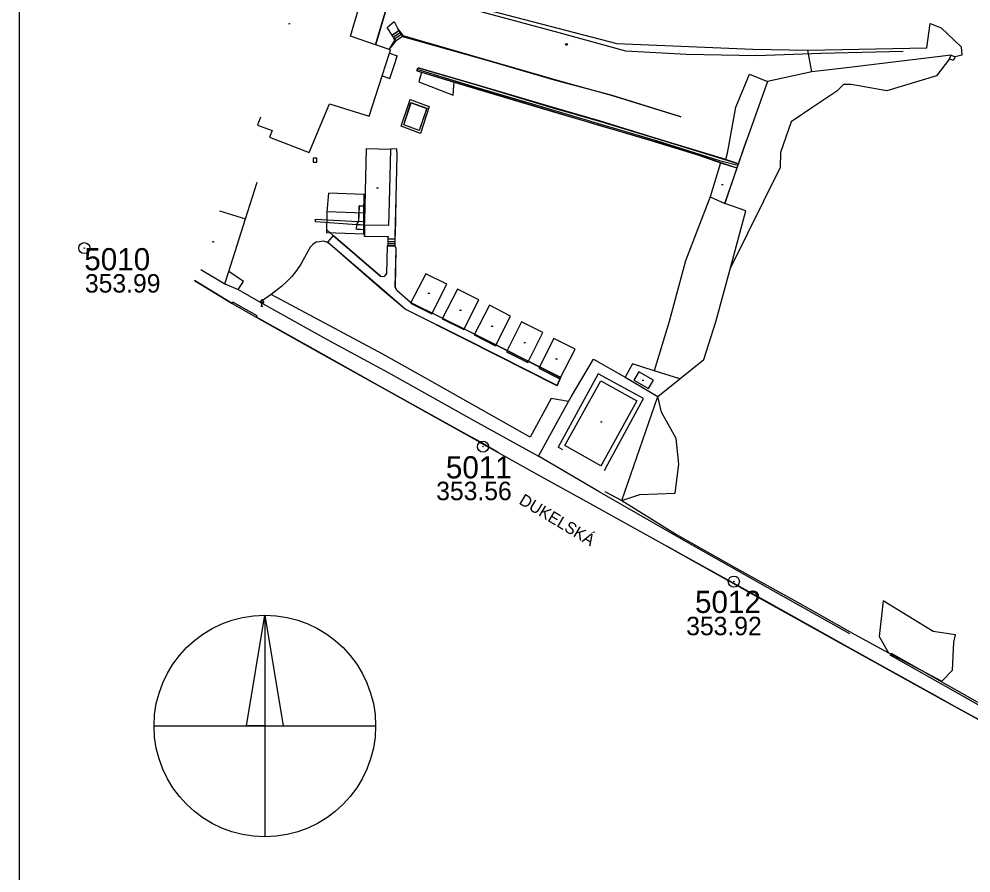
# Model space of a CAD drawing. Extents: x -590420 to -590210, y -1129531 to -1129234.
# Drawn here: x -590420.4 to -590291.5, y -1129429.2 to -1129313.6 of the extents above; entities that cross this region are included whole.
import ezdxf

# ---------------------------------------------------------------- set-up
doc = ezdxf.new("R2010")
doc.units = 0
for name, color, linetype in [('Vrstva 1', 7, 'Continuous'), ('Vrstva 10', 7, 'Continuous'), ('Vrstva 12', 7, 'Continuous'), ('Vrstva 15', 7, 'Continuous'), ('Vrstva 17', 7, 'Continuous'), ('Vrstva 19', 7, 'Continuous'), ('Vrstva 23', 7, 'Continuous'), ('Vrstva 4', 7, 'Continuous'), ('Vrstva 42', 7, 'Continuous'), ('Vrstva 5', 7, 'Continuous'), ('Vrstva 63', 7, 'Continuous'), ('Vrstva 7', 7, 'Continuous'), ('Vrstva B58', 7, 'Continuous'), ('Vrstva B59', 7, 'Continuous'), ('Vrstva B60', 7, 'Continuous')]:
    doc.layers.add(name, color=color, linetype=linetype)

msp = doc.modelspace()

# ---------------------------------------------------------------- linework, layer by layer
at = {"layer": 'Vrstva 1'}
for p, q in [((-590387.12, -1129394.3), (-590384.62, -1129409.3)), ((-590402.12, -1129409.3), (-590372.12, -1129409.3)), ((-590387.12, -1129409.3), (-590387.12, -1129424.3))]:
    msp.add_line(p, q, dxfattribs=at)
msp.add_lwpolyline([(-590387.12, -1129394.3), (-590387.12, -1129409.3), (-590389.62, -1129409.3)], close=True, dxfattribs=at)
msp.add_circle((-590387.12, -1129409.3), 15, dxfattribs=at)
at = {"layer": 'Vrstva 10'}
for p, q in [((-590313.04, -1129320.72), (-590313.58, -1129317.8)), ((-590392.54, -1129349.45), (-590390.72, -1129350.19)), ((-590302.66, -1129399.41), (-590295.44, -1129403.23))]:
    msp.add_line(p, q, dxfattribs=at)
for points in [[(-590366.23, -1129309.86), (-590365.68, -1129310.01), (-590339.47, -1129316.88), (-590321.05, -1129317.64), (-590313.58, -1129317.8), (-590297.47, -1129317.49), (-590297.03, -1129314.18)], [(-590294.16, -1129318.45), (-590308.7, -1129320.21), (-590313.04, -1129320.72), (-590319.06, -1129322.02), (-590321.88, -1129330.01)], [(-590366.52, -1129320.36), (-590358.42, -1129322.86), (-590348.3, -1129325.83), (-590342.1, -1129327.67), (-590334.13, -1129330.02), (-590325.54, -1129332.72), (-590323.05, -1129333.35)], [(-590338.76, -1129378.79), (-590333.91, -1129364.67), (-590330.93, -1129362.29), (-590327.65, -1129359.66), (-590326.02, -1129354.56), (-590324.05, -1129347.29), (-590321.96, -1129339.53)], [(-590387.74, -1129351.91), (-590378.78, -1129356.92), (-590370.43, -1129361.45), (-590358.74, -1129367.97), (-590350.07, -1129372.77), (-590345.99, -1129365.39), (-590345.63, -1129364.73), (-590342.63, -1129359.64), (-590338.32, -1129362.06), (-590333.91, -1129364.67)], [(-590330.93, -1129362.29), (-590334.4, -1129361.2), (-590337.34, -1129360.28), (-590338.32, -1129362.06)], [(-590341.07, -1129377.57), (-590338.76, -1129378.79), (-590331.36, -1129383.37), (-590323.3, -1129387.92), (-590314.97, -1129392.54), (-590307.2, -1129396.9)]]:
    msp.add_lwpolyline(points, dxfattribs=at)
at = {"layer": 'Vrstva 12'}
for p, q in [((-590322.98, -1129333.19), (-590321.88, -1129330.01)), ((-590321.88, -1129330.01), (-590321.88, -1129330.05)), ((-590321.88, -1129330.05), (-590321.88, -1129330.01)), ((-590323.18, -1129333.71), (-590323.18, -1129333.71)), ((-590324.84, -1129338.54), (-590324.83, -1129338.54))]:
    msp.add_line(p, q, dxfattribs=at)
for points in [[(-590321.96, -1129339.53), (-590324.83, -1129338.54), (-590321.88, -1129330.05)], [(-590389.75, -1129340.65), (-590388.17, -1129335.66)], [(-590321.96, -1129339.53), (-590324.84, -1129338.54)]]:
    msp.add_lwpolyline(points, dxfattribs=at)
at = {"layer": 'Vrstva 15'}
for p, q in [((-590371.98, -1129336.43), (-590371.73, -1129336.43)), ((-590325.28, -1129335.98), (-590325.03, -1129335.98)), ((-590365.04, -1129350.7), (-590364.79, -1129350.7)), ((-590360.75, -1129353), (-590360.5, -1129353)), ((-590356.46, -1129355.18), (-590356.21, -1129355.18)), ((-590352.06, -1129357.4), (-590351.81, -1129357.4)), ((-590347.75, -1129359.61), (-590347.5, -1129359.61)), ((-590336.02, -1129362.46), (-590335.77, -1129362.46))]:
    msp.add_line(p, q, dxfattribs=at)
for centre in [(-590383.81, -1129314.21), (-590394.12, -1129343.75), (-590341.55, -1129368.12)]:
    msp.add_circle(centre, 0.0438, dxfattribs=at)
at = {"layer": 'Vrstva 17'}
for p, q in [((-590368.45, -1129315.79), (-590368.44, -1129315.98)), ((-590366.53, -1129320.51), (-590366.37, -1129320.17))]:
    msp.add_line(p, q, dxfattribs=at)
for points in [[(-590369.09, -1129314.9), (-590368.45, -1129315.79), (-590357.35, -1129319.03), (-590347.55, -1129321.85), (-590340.2, -1129323.9), (-590330.87, -1129326.76)], [(-590330.87, -1129326.76), (-590330.78, -1129326.81), (-590340.21, -1129323.9), (-590347.59, -1129321.93), (-590357.33, -1129319.09), (-590368.44, -1129315.98), (-590368.47, -1129315.94), (-590368.47, -1129315.93), (-590368.63, -1129315.68), (-590368.63, -1129315.67), (-590368.78, -1129315.43), (-590368.77, -1129315.43), (-590368.94, -1129315.16), (-590368.94, -1129315.15), (-590369.09, -1129314.9)], [(-590370.28, -1129317.7), (-590369.5, -1129316.48), (-590369.68, -1129316.05)], [(-590370.28, -1129317.7), (-590369.35, -1129316.53)], [(-590366.53, -1129320.51), (-590366.52, -1129320.61), (-590366.49, -1129320.58), (-590366.36, -1129320.17), (-590366.37, -1129320.17)], [(-590322.98, -1129333.19), (-590325.29, -1129332.42), (-590333.94, -1129329.8), (-590341.66, -1129327.43), (-590348.2, -1129325.53), (-590358.47, -1129322.48), (-590366.37, -1129320.17)], [(-590366.36, -1129320.17), (-590358.47, -1129322.51), (-590348.24, -1129325.54), (-590341.65, -1129327.44), (-590333.95, -1129329.82), (-590325.27, -1129332.45), (-590322.98, -1129333.19), (-590323.18, -1129333.71)], [(-590366.52, -1129320.61), (-590365.91, -1129320.79), (-590361.5, -1129322.12), (-590358.65, -1129322.98), (-590353.95, -1129324.38), (-590348.16, -1129326.11), (-590341.84, -1129327.97), (-590334.96, -1129329.96), (-590328.36, -1129332.02), (-590325.39, -1129333.03)], [(-590366.49, -1129320.58), (-590358.63, -1129322.95), (-590353.95, -1129324.36), (-590348.34, -1129326.03), (-590341.73, -1129327.98), (-590335.04, -1129329.93), (-590334.09, -1129330.2), (-590328.47, -1129331.94), (-590325.38, -1129333.02), (-590323.18, -1129333.71)]]:
    msp.add_lwpolyline(points, dxfattribs=at)
at = {"layer": 'Vrstva 19'}
for p, q in [((-590387.52, -1129351.54), (-590387.77, -1129351.97)), ((-590387.77, -1129351.97), (-590387.27, -1129351.97)), ((-590387.65, -1129352.47), (-590387.4, -1129352.47)), ((-590387.52, -1129351.54), (-590387.27, -1129351.97)), ((-590387.52, -1129352.47), (-590387.52, -1129351.97))]:
    msp.add_line(p, q, dxfattribs=at)
at = {"layer": 'Vrstva 23'}
for p, q in [((-590380.07, -1129332.44), (-590380.57, -1129332.44)), ((-590380.57, -1129332.44), (-590380.57, -1129332.94)), ((-590380.57, -1129332.94), (-590380.07, -1129332.94)), ((-590380.07, -1129332.94), (-590380.07, -1129332.44))]:
    msp.add_line(p, q, dxfattribs=at)
msp.add_circle((-590346.26, -1129317.01), 0.125, dxfattribs=at)
at = {"layer": 'Vrstva 4'}
for p, q in [((-590370.25, -1129318.21), (-590369.18, -1129318.57)), ((-590387.72, -1129326.88), (-590388.1, -1129327.96)), ((-590325.39, -1129333.03), (-590323.18, -1129333.71)), ((-590323.18, -1129333.71), (-590324.84, -1129338.54)), ((-590373.65, -1129337.33), (-590378.52, -1129337.16)), ((-590393.27, -1129339.53), (-590389.75, -1129340.65)), ((-590373.69, -1129339.87), (-590378.72, -1129339.69)), ((-590373.73, -1129342.7), (-590378.76, -1129342.52))]:
    msp.add_line(p, q, dxfattribs=at)
for points in [[(-590386.47, -1129329.57), (-590381.1, -1129331.63), (-590378.34, -1129325.04), (-590372.97, -1129326.72), (-590372.97, -1129326.71), (-590371.23, -1129321.27), (-590370.25, -1129318.21), (-590370.11, -1129317.76), (-590370.28, -1129317.7), (-590370.28, -1129317.7), (-590372.1, -1129317.05), (-590372.11, -1129317.05), (-590375.5, -1129315.91), (-590374.48, -1129312.38), (-590374.83, -1129312.27), (-590382.92, -1129309.78), (-590391.01, -1129307.15), (-590391.04, -1129307.14), (-590391.04, -1129307.14), (-590391.08, -1129307.26), (-590391.08, -1129307.27), (-590391.87, -1129309.84)], [(-590371.23, -1129321.27), (-590370.19, -1129321.61), (-590369.43, -1129319.32), (-590369.18, -1129318.57)], [(-590388.1, -1129327.96), (-590386.12, -1129328.66), (-590386.47, -1129329.57)], [(-590325.39, -1129333.03), (-590326.83, -1129337.64), (-590324.84, -1129338.54)], [(-590378.52, -1129337.16), (-590378.72, -1129339.69), (-590378.76, -1129342.52)], [(-590373.73, -1129342.7), (-590373.69, -1129339.87), (-590373.65, -1129337.33)], [(-590395.8, -1129347.51), (-590392.54, -1129349.45), (-590392.01, -1129347.78), (-590389.75, -1129340.65)], [(-590336.74, -1129365.27), (-590341.29, -1129373.53), (-590341.6, -1129374.1), (-590346.49, -1129371.31), (-590341.6, -1129362.58), (-590336.74, -1129365.27)]]:
    msp.add_lwpolyline(points, dxfattribs=at)
for points in [[(-590373.6, -1129341.44), (-590373.59, -1129341.03), (-590373.59, -1129341.03), (-590373.54, -1129338.89), (-590373.54, -1129338.87), (-590373.34, -1129331.1), (-590370.12, -1129331.22), (-590370.23, -1129336.69), (-590370.37, -1129341.55), (-590373.6, -1129341.48)], [(-590364.49, -1129353.51), (-590362.46, -1129349.48), (-590365.33, -1129348.07), (-590367.39, -1129352.06)], [(-590360.19, -1129355.62), (-590358.16, -1129351.61), (-590361.04, -1129350.15), (-590363.09, -1129354.19)], [(-590355.9, -1129357.84), (-590353.83, -1129353.83), (-590356.7, -1129352.33), (-590358.78, -1129356.35)], [(-590354.37, -1129358.65), (-590351.48, -1129360.07), (-590349.47, -1129356.02), (-590352.37, -1129354.57)], [(-590347.15, -1129362.32), (-590345.09, -1129358.3), (-590347.99, -1129356.83), (-590350.03, -1129360.84)], [(-590334.5, -1129362.5), (-590336.46, -1129361.33), (-590337.14, -1129362.46), (-590335.18, -1129363.63)]]:
    msp.add_lwpolyline(points, close=True, dxfattribs=at)
at = {"layer": 'Vrstva 5'}
for points in [[(-590390.72, -1129350.19), (-590387.74, -1129351.91)], [(-590307.2, -1129396.9), (-590302.66, -1129399.41)]]:
    msp.add_lwpolyline(points, dxfattribs=at)
at = {"layer": 'Vrstva 63'}
msp.add_line((-590420.41, -1129233.85), (-590420.41, -1129530.85), dxfattribs=at)
at = {"layer": 'Vrstva 7'}
for p, q in [((-590372.1, -1129317.05), (-590369.65, -1129308.79)), ((-590372.11, -1129317.05), (-590370.41, -1129311.35)), ((-590367.45, -1129324.49), (-590367.45, -1129324.48)), ((-590367.33, -1129324.9), (-590367.32, -1129324.92)), ((-590364.87, -1129325.41), (-590364.86, -1129325.41)), ((-590365.18, -1129325.67), (-590365.2, -1129325.68)), ((-590368.3, -1129327.9), (-590368.28, -1129327.89)), ((-590368.64, -1129328.07), (-590368.65, -1129328.07)), ((-590366.22, -1129328.67), (-590366.23, -1129328.65)), ((-590366.03, -1129329.08), (-590366.03, -1129329.09)), ((-590380.25, -1129341.05), (-590380.26, -1129340.7)), ((-590374.72, -1129342.02), (-590374.67, -1129341.45)), ((-590374.72, -1129342.02), (-590373.61, -1129342.08)), ((-590374.69, -1129341.98), (-590373.61, -1129342.06)), ((-590374.67, -1129341.45), (-590374.66, -1129341.45)), ((-590374.65, -1129341.36), (-590373.6, -1129341.44)), ((-590374.65, -1129341.38), (-590373.6, -1129341.45)), ((-590373.59, -1129341.03), (-590374.37, -1129341.01)), ((-590373.59, -1129341.03), (-590374.37, -1129341.01)), ((-590371.47, -1129348.41), (-590377.86, -1129342.87)), ((-590373.61, -1129343), (-590373.63, -1129343.01)), ((-590370.46, -1129343.07), (-590373.63, -1129343.01)), ((-590370.43, -1129343.04), (-590370.46, -1129343.07)), ((-590370.44, -1129343.36), (-590369.45, -1129343.35)), ((-590370.44, -1129343.37), (-590369.45, -1129343.36)), ((-590369.46, -1129343.69), (-590369.45, -1129343.36)), ((-590369.45, -1129343.36), (-590369.45, -1129342.88)), ((-590370.54, -1129344.29), (-590370.63, -1129348.07)), ((-590370.61, -1129348.08), (-590370.52, -1129344.3)), ((-590370.46, -1129344.3), (-590370.54, -1129344.29)), ((-590370.46, -1129344.3), (-590370.52, -1129344.3)), ((-590370.45, -1129344.29), (-590370.46, -1129344.3)), ((-590370.45, -1129343.99), (-590369.46, -1129343.98)), ((-590369.46, -1129344.31), (-590370.45, -1129344.29)), ((-590370.44, -1129343.69), (-590369.46, -1129343.68)), ((-590370.44, -1129343.7), (-590369.46, -1129343.69)), ((-590370.44, -1129343.98), (-590369.46, -1129343.97)), ((-590369.46, -1129343.98), (-590369.46, -1129343.69)), ((-590369.45, -1129344.32), (-590369.46, -1129343.98)), ((-590396.65, -1129348.98), (-590391.56, -1129352.1)), ((-590391.56, -1129352.11), (-590391.46, -1129351.92)), ((-590391.56, -1129352.11), (-590388.29, -1129353.97)), ((-590388.29, -1129353.97), (-590388.17, -1129353.76)), ((-590347.54, -1129363.23), (-590347.04, -1129362.14)), ((-590347.54, -1129363.2), (-590347.06, -1129362.15)), ((-590347.54, -1129363.23), (-590347.54, -1129363.2)), ((-590346.78, -1129371.89), (-590347.38, -1129371.57)), ((-590341.74, -1129377.64), (-590350.07, -1129372.77)), ((-590341.12, -1129374.7), (-590340.67, -1129373.87)), ((-590302.26, -1129399.47), (-590302.41, -1129399.73))]:
    msp.add_line(p, q, dxfattribs=at)
for points in [[(-590300.68, -1129317.99), (-590311.82, -1129318.26), (-590320.49, -1129318.55), (-590330.07, -1129318.36), (-590338.22, -1129317.93), (-590347.27, -1129315.46), (-590357.99, -1129312.56), (-590368.83, -1129311.54)], [(-590369.86, -1129315.78), (-590370.53, -1129314.71), (-590369.59, -1129313.92), (-590369.09, -1129314.9)], [(-590297.03, -1129314.18), (-590295.53, -1129314.77), (-590292.83, -1129317.33), (-590292.72, -1129318.48), (-590293.65, -1129318.68)], [(-590368.94, -1129315.15), (-590369.86, -1129315.78)], [(-590368.94, -1129315.16), (-590369.86, -1129315.79)], [(-590369.35, -1129316.53), (-590369.35, -1129316.53), (-590369.52, -1129316.28), (-590369.52, -1129316.28), (-590369.68, -1129316.05), (-590369.68, -1129316.04), (-590369.86, -1129315.79), (-590369.86, -1129315.78)], [(-590368.78, -1129315.43), (-590369.68, -1129316.05)], [(-590368.77, -1129315.43), (-590369.68, -1129316.04)], [(-590368.63, -1129315.67), (-590369.52, -1129316.28)], [(-590368.63, -1129315.68), (-590369.52, -1129316.28)], [(-590368.47, -1129315.93), (-590369.35, -1129316.53)], [(-590368.47, -1129315.94), (-590369.35, -1129316.53)], [(-590294.39, -1129318.95), (-590296.17, -1129321.25), (-590302.9, -1129323.29), (-590307.7, -1129322.45), (-590308.75, -1129322.43), (-590309.67, -1129323.33), (-590312.9, -1129325.5), (-590315.83, -1129327.48), (-590317.29, -1129331.67), (-590317.34, -1129333.7), (-590324.05, -1129347.29)], [(-590365.91, -1129320.79), (-590366.26, -1129322.1), (-590361.61, -1129323.87), (-590361.53, -1129322.59), (-590361.5, -1129322.12)], [(-590324.7, -1129332.62), (-590324.45, -1129331.74), (-590323.33, -1129325.53), (-590321.5, -1129321.03), (-590319.06, -1129322.02)], [(-590368.28, -1129327.89), (-590367.32, -1129324.92), (-590365.2, -1129325.68), (-590366.23, -1129328.65), (-590368.28, -1129327.89)], [(-590369.19, -1129331.94), (-590369.23, -1129331.16), (-590370.12, -1129331.22)], [(-590369.45, -1129343.35), (-590369.45, -1129342.88), (-590369.34, -1129337.86), (-590369.19, -1129331.94)], [(-590369.45, -1129342.88), (-590369.42, -1129342.87), (-590369.33, -1129337.86), (-590369.19, -1129331.94)], [(-590326.83, -1129337.64), (-590330.17, -1129346.32), (-590332.34, -1129354.55), (-590334.4, -1129361.2)], [(-590374.38, -1129340.99), (-590374.33, -1129338.87), (-590373.54, -1129338.87)], [(-590374.37, -1129341.01), (-590374.32, -1129338.88), (-590373.54, -1129338.89)], [(-590374.32, -1129338.88), (-590374.33, -1129338.87)], [(-590380.26, -1129340.7), (-590374.54, -1129340.98), (-590374.38, -1129340.99)], [(-590374.67, -1129341.45), (-590380.25, -1129341.05)], [(-590377.86, -1129342.87), (-590378.68, -1129342.16)], [(-590377.86, -1129342.87), (-590378.68, -1129342.16)], [(-590374.72, -1129342.02), (-590374.69, -1129341.98), (-590374.66, -1129341.45), (-590374.65, -1129341.38), (-590374.65, -1129341.36)], [(-590374.54, -1129340.98), (-590374.67, -1129341.37), (-590374.67, -1129341.45)], [(-590374.65, -1129341.36), (-590374.37, -1129341.01)], [(-590374.38, -1129340.99), (-590374.37, -1129341.01), (-590374.37, -1129341.01)], [(-590373.63, -1129343.01), (-590373.61, -1129342.08), (-590373.61, -1129342.06), (-590373.6, -1129341.45), (-590373.6, -1129341.44)], [(-590373.6, -1129341.48), (-590373.61, -1129343), (-590370.43, -1129343.04)], [(-590377.86, -1129342.87), (-590378.56, -1129343.72), (-590378.65, -1129343.83)], [(-590377.86, -1129342.87), (-590371.47, -1129348.41)], [(-590370.46, -1129343.07), (-590370.46, -1129344.3)], [(-590370.44, -1129343.36), (-590370.44, -1129343.37), (-590370.44, -1129343.69), (-590370.44, -1129343.7), (-590370.44, -1129343.98), (-590370.45, -1129343.99), (-590370.45, -1129344.29)], [(-590370.43, -1129343.04), (-590370.44, -1129343.36)], [(-590369.45, -1129344.32), (-590369.46, -1129344.31), (-590369.46, -1129343.98), (-590369.46, -1129343.97), (-590369.46, -1129343.69), (-590369.46, -1129343.68), (-590369.45, -1129343.36), (-590369.45, -1129343.35)], [(-590347.54, -1129363.2), (-590359.76, -1129357.04), (-590368.1, -1129352.88), (-590371.24, -1129350.16), (-590378.31, -1129344.05), (-590378.65, -1129343.83), (-590378.74, -1129343.78), (-590379.22, -1129343.64), (-590379.71, -1129343.73), (-590380.18, -1129343.8), (-590380.6, -1129344.09), (-590380.97, -1129344.45), (-590382.24, -1129346.76), (-590382.81, -1129347.62), (-590383.48, -1129348.46), (-590384.14, -1129349.13), (-590384.85, -1129349.79), (-590386.27, -1129350.86), (-590387.74, -1129351.91)], [(-590347.54, -1129363.23), (-590359.76, -1129357.05), (-590368.11, -1129352.88), (-590371.26, -1129350.18), (-590378.31, -1129344.06), (-590378.74, -1129343.78)], [(-590370.46, -1129344.3), (-590369.45, -1129344.32)], [(-590369.34, -1129344.64), (-590369.45, -1129344.32)], [(-590347.06, -1129362.15), (-590359.26, -1129355.99), (-590367.38, -1129351.96), (-590369.25, -1129350.35), (-590369.45, -1129349.9), (-590369.34, -1129344.64)], [(-590347.04, -1129362.14), (-590359.26, -1129355.98), (-590367.37, -1129351.95), (-590369.24, -1129350.32), (-590369.44, -1129349.9), (-590369.33, -1129344.64)], [(-590369.33, -1129344.64), (-590369.34, -1129344.64)], [(-590390.72, -1129350.19), (-590390, -1129349.11), (-590392.01, -1129347.78)], [(-590391.56, -1129352.1), (-590391.56, -1129352.11), (-590396.65, -1129349)], [(-590345.99, -1129365.39), (-590348.34, -1129364.94), (-590351.2, -1129370.21), (-590364.44, -1129362.7), (-590371.12, -1129358.98), (-590386.27, -1129350.86)], [(-590388.27, -1129353.96), (-590388.17, -1129353.76), (-590391.46, -1129351.92), (-590391.56, -1129352.1)], [(-590355.52, -1129372.26), (-590357.14, -1129371.31), (-590357.97, -1129370.84), (-590359.73, -1129369.89), (-590371.5, -1129363.33), (-590379.85, -1129358.65), (-590388.27, -1129353.96), (-590388.29, -1129353.97)], [(-590388.29, -1129353.97), (-590379.87, -1129358.7), (-590371.52, -1129363.35), (-590359.77, -1129369.89), (-590358.02, -1129370.87), (-590357.16, -1129371.35), (-590355.52, -1129372.26), (-590351, -1129374.8), (-590342.74, -1129379.37), (-590332.57, -1129385.02), (-590330.82, -1129386.01), (-590319.93, -1129392.08), (-590307.83, -1129398.82), (-590295.9, -1129405.45), (-590293.78, -1129406.63), (-590284.05, -1129411.95)], [(-590340.67, -1129373.87), (-590335.84, -1129364.96), (-590341.99, -1129361.62), (-590347.38, -1129371.57)], [(-590347.04, -1129362.14), (-590347.06, -1129362.15)], [(-590338.76, -1129378.79), (-590336.32, -1129377.94), (-590331.56, -1129377.76), (-590331.05, -1129373.84), (-590331.43, -1129370.37), (-590333.39, -1129366.83), (-590333.91, -1129364.67)], [(-590307.89, -1129396.82), (-590319.01, -1129390.58), (-590330.09, -1129384.31), (-590341.74, -1129377.64)], [(-590284.03, -1129411.94), (-590293.77, -1129406.61), (-590295.91, -1129405.41), (-590307.82, -1129398.81), (-590319.92, -1129392.05), (-590330.83, -1129385.99), (-590332.57, -1129385.02)], [(-590295.44, -1129403.23), (-590294, -1129401.73), (-590293.82, -1129397.94), (-590293.59, -1129396.98), (-590296.63, -1129396.49), (-590303.38, -1129392.36), (-590303.9, -1129397.17), (-590302.66, -1129399.41)], [(-590283.85, -1129410.23), (-590294.91, -1129403.98), (-590302.41, -1129399.73)], [(-590283.76, -1129409.94), (-590294.76, -1129403.72), (-590302.26, -1129399.47)]]:
    msp.add_lwpolyline(points, dxfattribs=at)
for points in [[(-590294.16, -1129318.45), (-590293.65, -1129318.68), (-590293.88, -1129319.19), (-590294.39, -1129318.95)], [(-590368.65, -1129328.07), (-590367.45, -1129324.48), (-590364.86, -1129325.41), (-590366.03, -1129329.09)], [(-590368.64, -1129328.07), (-590367.45, -1129324.49), (-590364.87, -1129325.41), (-590366.03, -1129329.08)], [(-590368.3, -1129327.9), (-590367.33, -1129324.9), (-590365.18, -1129325.67), (-590366.22, -1129328.67)]]:
    msp.add_lwpolyline(points, close=True, dxfattribs=at)
for centre, major_axis, ratio, start_param, end_param in [((-590371.22, -1129347.8), (0.606, 0.243), 0.993874, 3.949397, 5.475381), ((-590371.23, -1129347.76), (0.697, 0.014), 0.99949, 4.338042, 5.78064)]:
    msp.add_ellipse(centre, major_axis=major_axis, ratio=ratio, start_param=start_param, end_param=end_param, dxfattribs=at)
at = {"layer": 'Vrstva B60'}
for centre, radius in [((-590411.57, -1129344.6), 0.75), ((-590411.57, -1129344.6), 0.0358), ((-590357.57, -1129371.48), 0.75), ((-590357.57, -1129371.48), 0.0358), ((-590323.6, -1129389.75), 0.75), ((-590323.6, -1129389.75), 0.0358)]:
    msp.add_circle(centre, radius, dxfattribs=at)

# ---------------------------------------------------------------- texts
at = {"layer": 'Vrstva 42'}
msp.add_text('DUKELSKÁ', height=1.6, rotation=329.0755, dxfattribs=at).set_placement((-590352.82, -1129379.15))
at = {"layer": 'Vrstva B58'}
for s, p in [('353.99', (-590411.48, -1129350.62)), ('353.56', (-590363.91, -1129378.73)), ('353.92', (-590330.05, -1129397.02))]:
    msp.add_text(s, height=2.5, dxfattribs=at).set_placement(p)
at = {"layer": 'Vrstva B59'}
for s, p in [('5010', (-590411.57, -1129347.6)), ('5011', (-590362.6, -1129375.78)), ('5012', (-590328.86, -1129394))]:
    msp.add_text(s, height=3, dxfattribs=at).set_placement(p)

doc.saveas('drawing.dxf')
